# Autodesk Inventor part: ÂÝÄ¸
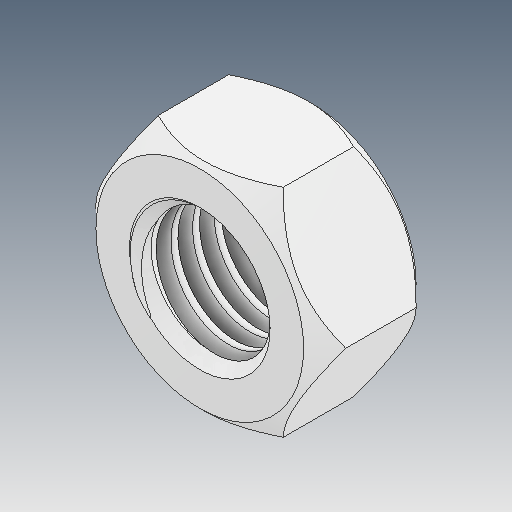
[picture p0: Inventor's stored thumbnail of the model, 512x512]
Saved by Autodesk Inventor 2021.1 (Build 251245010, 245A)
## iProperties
Created: 2021-06
Part Number: ÂÝÄ¸
Material: Ogólny
Document SubType Name: Modeling
Designer: user
Density: 1 g/cm^3
Appearance: Domyślna
Author: user
Revision Number: ÈÎºÎ
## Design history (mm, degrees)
feature "ÇÐ³ý-É¨Ãè1"
node "Bryła1"
